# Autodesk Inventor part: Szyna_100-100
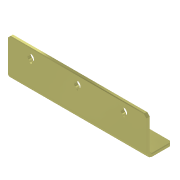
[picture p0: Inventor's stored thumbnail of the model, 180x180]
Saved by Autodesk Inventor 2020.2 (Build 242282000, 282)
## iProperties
Created: 2010-12
Part Number: Szyna_100-100
Document SubType Name: Modeling
Designer: F.Stasiak
Density: 1 g/cm^3
Material: Ogólny
Appearance: Nikiel
Manager: www.cadconsulting.pl
Company: Fabian Stasiak CAD Consulting
Author: F.Stasiak
Subject: Zbiór ćwiczeń. Autodesk Inventor 2020. Kurs podstawowy
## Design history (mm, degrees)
sketch "Szkic1"
  geometry: L1 (0, 0)-(0, 70); L2 (0, 70)-(6, 70); L3 (6, 70)-(6, 6); L4 (6, 6)-(46, 6); L5 (46, 6)-(46, 0); L6 (46, 0)-(0, 0); 1 further point
  constraints: 12 end point, 4 parallel, 1 coincident, 1 perpendicular, 1 vertical
  dimensions: "d0" = 70 distance of L1.start L1.end; "d1" = 6 distance of L1.end L2.end; "d3" = 40 distance of L3.end L4.end; "d4" = 6 distance of L4.end L5.end
extrude "Wyciągnięcie proste1" new body sketch "Szkic1" stored distance "d5" = 250; taper "d6" = 0 deg
fillet "Zaokrąglenie1" dims "d7" = 5, "d8" = 11
sketch "Szkic2"
  geometry: L1 (250, -59)-(0, -59) reference; L2 (250, 0)-(0, 0) reference; L3 (125, 0)-(125, -59); L4 (0, 0)-(0, -59) reference; L5 (41.667, -15)-(208.333, -15); 6 further points
  constraints: 4 end point, 4 midpoint, 3 coincident, 1 perpendicular, 1 point on line
  dimensions: "d28" = 166.66667 distance of L5.start L5.end (= 0.666667 x d5); "d29" = 15 distance between parallel lines of L2 L5
hole "Hole1" sketch "Szkic2" at (208.333, -15), (125, -15), (41.667, -15) diameter "d10" = 12; stored, may be unused: countersink angle "d14" = 90 deg, drill point angle "d16" = 118 deg; dims "d11" = 6, "d12" = 4, "d13" = 2, "d15" = 8
sketch "Szkic3"
  geometry: L1 (-35, 0)-(0, 0) reference; L2 (0, 250)-(-35, 250) reference; L3 (-17.5, 0)-(-17.5, 250); L4 (-11, 35)-(-11, 85); L5 (-24, 85)-(-24, 35); A1 r 6.5 centre (-17.5, 85) between (-11, 85) and (-24, 85); A2 r 6.5 centre (-17.5, 35) between (-24, 35) and (-11, 35); 1 further point
  constraints: 6 end point, 4 point on circle, 4 tangent, 2 centre point, 2 midpoint, 2 parallel, 1 point on line
  dimensions: "d17" = 50 distance of L4.start L4.end; "d18" = 6.5 radius of A2; "d19" = 35 distance from line of L1 A2.centre
extrude "Wyciągnięcie proste2" cut sketch "Szkic3" extent not by distance; stored distance "d20" = 250; taper "d21" = 0 deg
mirror "Odbicie lustrzane1"
chamfer "Faza1" distance "d22" = 5; stored, may be unused: second distance "d23" = 2, angle "d24" = 45 deg
chamfer "Faza2" distance "d25" = 1; stored, may be unused: second distance "d26" = 2, angle "d27" = 45 deg
sketch "Szkic4"
  geometry: L1 (0, 0)-(-248, 0) reference; L2 (-42.417, 38.261)-(-42.417, 35); L3 (-42.417, 35)-(-38.917, 35); L4 (-38.917, 35)-(-38.917, 38.261); A1 r 6 centre (-40.667, 44) between (-42.417, 38.261) and (-38.917, 38.261) reference; 1 further point
  constraints: 6 end point, 2 parallel, 2 perpendicular, 2 point on circle
  dimensions: "d39" = 3.5 distance of L2.end L3.end; "d40" = 9 distance from line of A1.centre L3
extrude "Wyciągnięcie proste3" cut sketch "Szkic4" extent not by distance; stored distance "d41" = 10; taper "d42" = 0 deg
pattern_linear "Szyk prostokątny1" dims "d45" = 83.33333 (= 0.5 x d28)
node "Bryła1"
